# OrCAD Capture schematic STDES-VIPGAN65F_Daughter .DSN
size A3
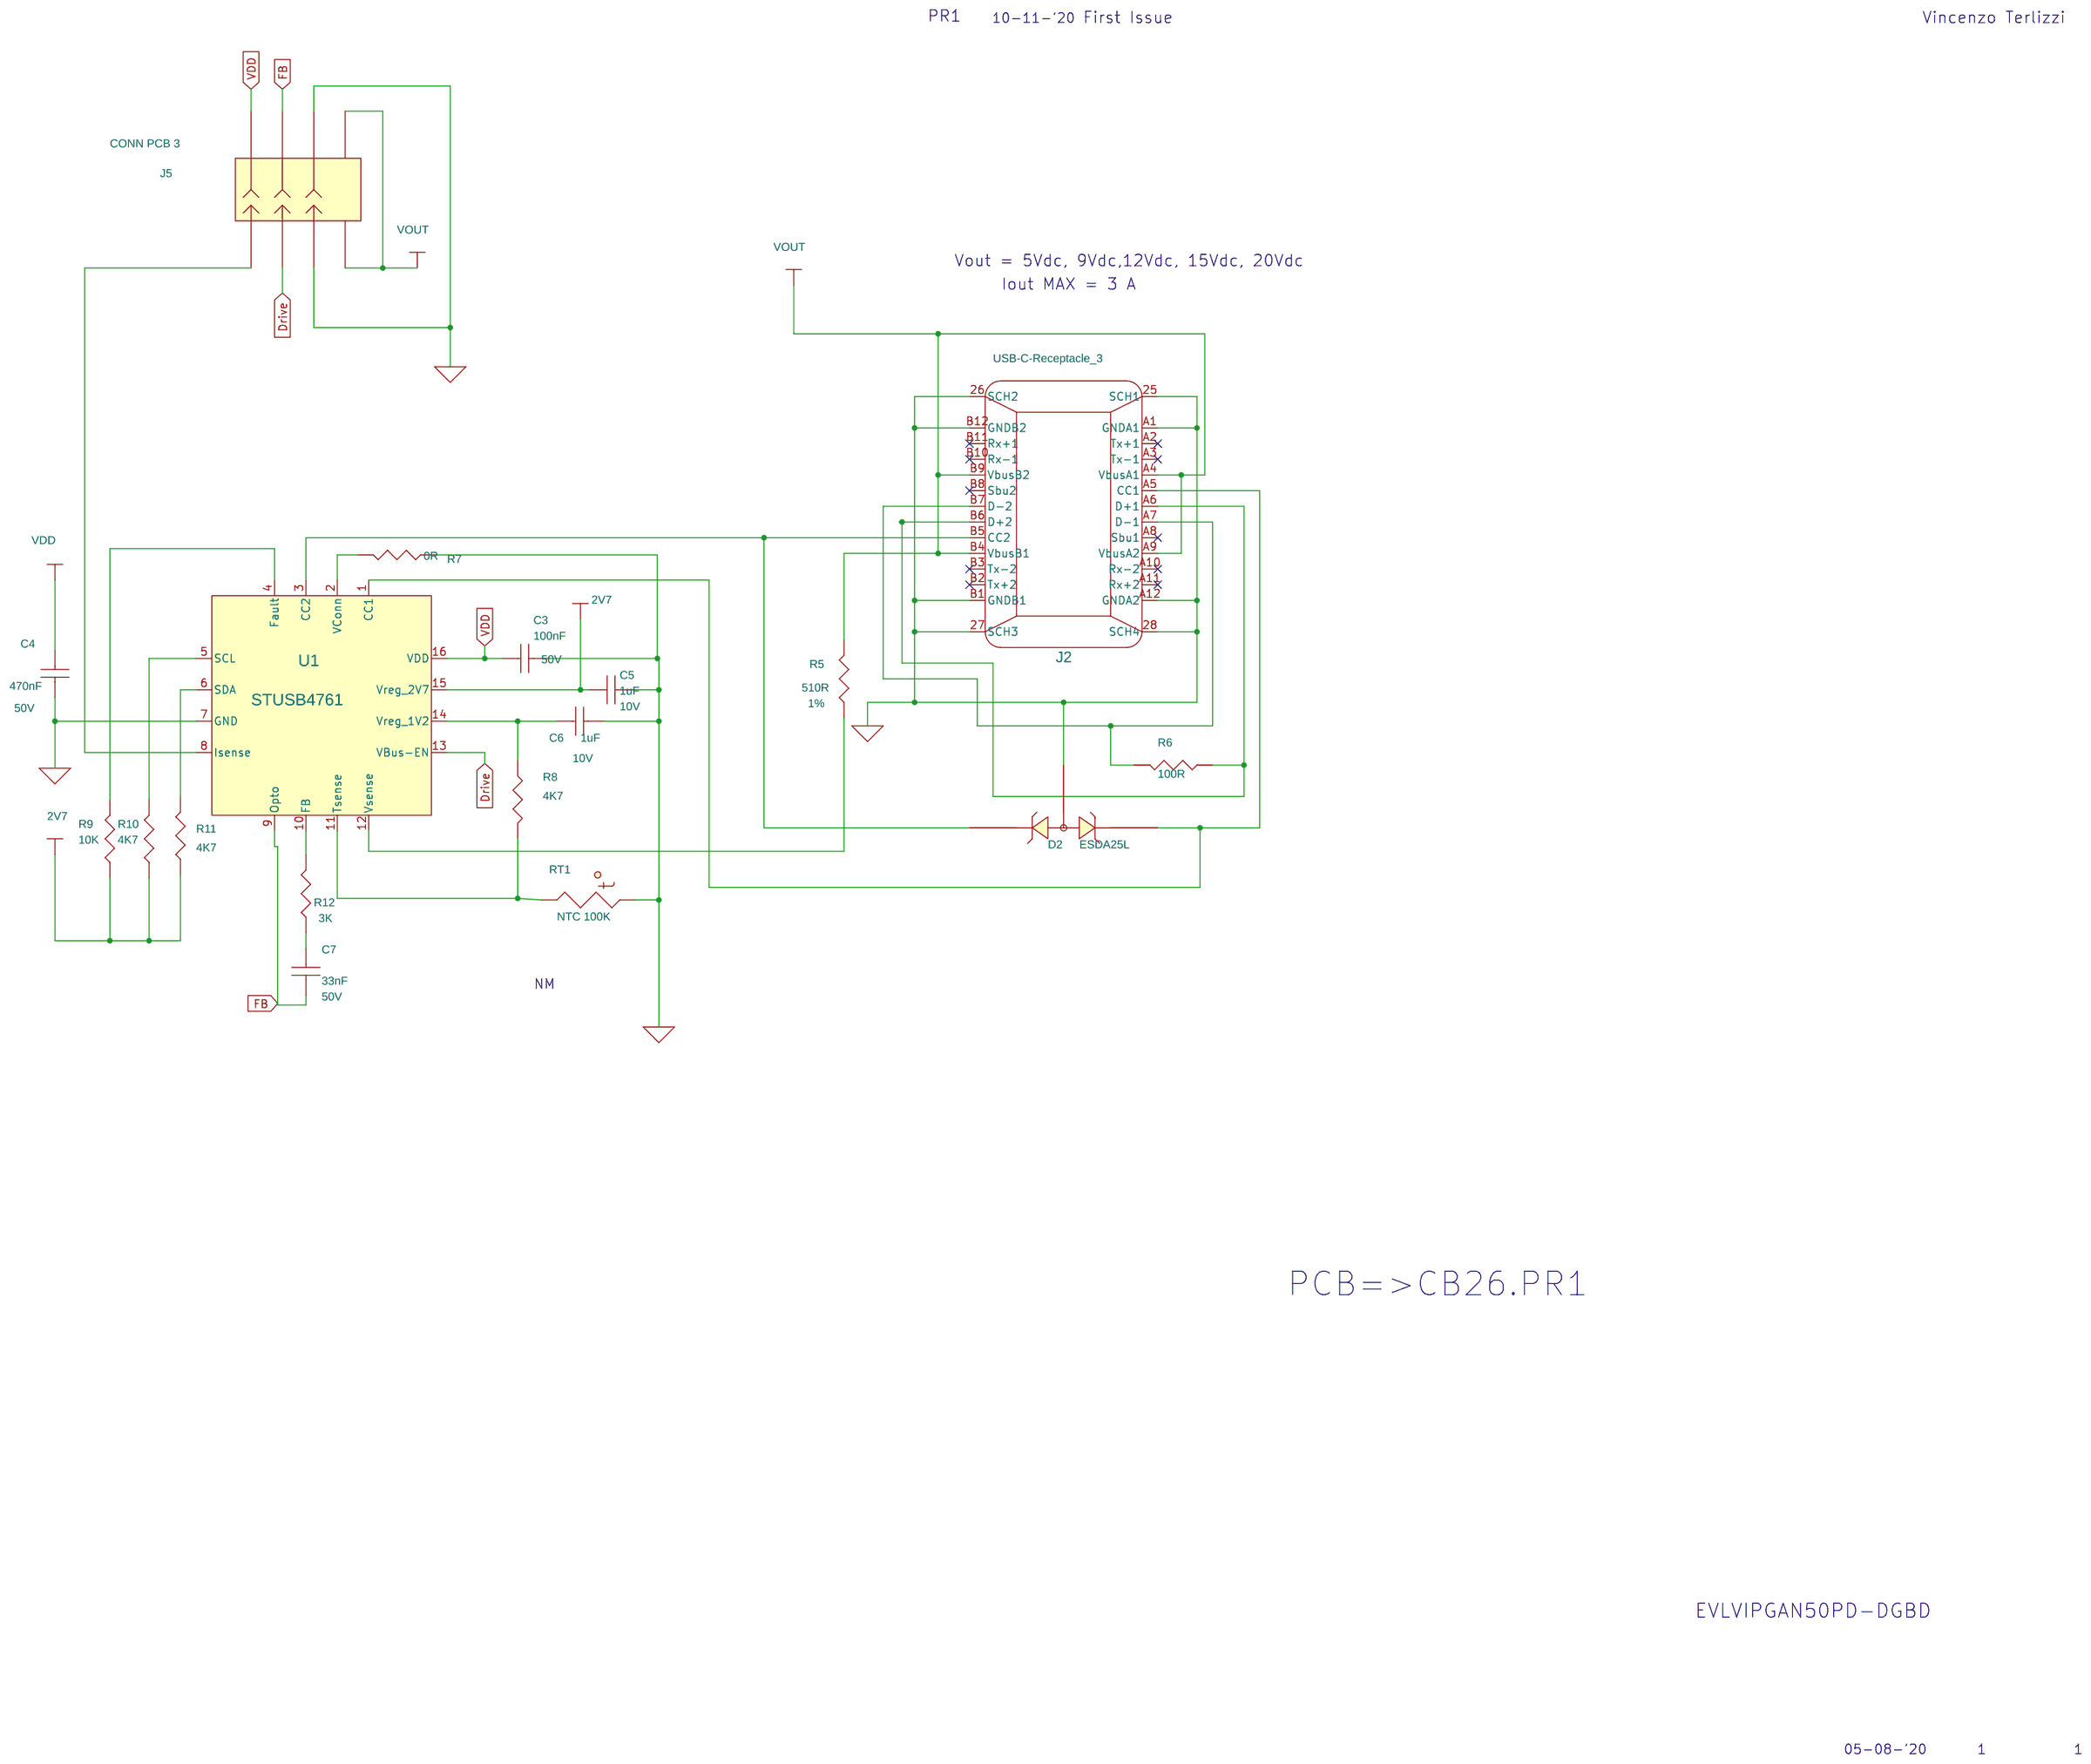
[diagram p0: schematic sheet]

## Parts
C3  100nF  [C_0402]
C4  470nF  [C_0603]
C5  1uF  [C_0402]
C6  1uF  [C_0402]
C7  33nF  [R_0402]
D2  ESDA25L  [sot23st]
J2  USB-C-Receptacle_3  [usbcsmtmolex_new]
J5  CONN PCB 3  [PD_sBOARD]
R5  510R  [R_0402]
R6  100R  [R_0402]
R7  0R  [R_0402]
R8  4K7  [R_0402]
R9  10K  [R_0402]
R10  4K7  [R_0402]
R11  4K7  [R_0402]
R12  3K  [R_0402]
RT1  NTC 100K  [R_0603]
U1  STUSB4761  [qfn16]

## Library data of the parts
C3 = CAP_NP: Multilayer Ceramic X7R   0.1uF       50V  10%; MFG: Kemet; MFG - Code: C0603C104K5RACTU; Manufacturer: Kemet; Manufacturer PN: C0603C104K5RACTU; Rating: 50V; Technology: Multilayer Ceramic Capacitor X7R; Tolerance: 10%
C4 = CAP_NP: Multilayer Ceramic X7R   0.47uF     50V  10%; MFG: AVX; MFG - Code: 08055C474K4T2A; Manufacturer: AVX; Manufacturer PN: 08055C474K4T2A; Rating: 50V; Technology: Multilayer Ceramic Capacitor X7R; Tolerance: 10%
C5 C6 = CAP_NP: Multilayer Ceramic X7R    1uF         50V  10%; MFG: Kemet; MFG - Code: C0805C105J4RACTU; Manufacturer: Kemet; Manufacturer PN: C0805C105J4RACTU; Rating: 10V; Technology: Multilayer Ceramic Capacitor X7R; Tolerance: 10%
C7 = CAP_NP: Multilayer Ceramic X7R   0.033uF   50V 10%; MFG: Kemet; Manufacturer: Kemet; Manufacturer PN: C0603X333K5X7RAC; Rating: 50V; Technology: Multilayer Ceramic Capacitor X7R; Tolerance: 10%
D2 = DIODE_DUAL_CA_JKK_2: Dual Transil   10mA - 1.2V; Manufacturer: STMicroelectronics
J2 = USB-C-Receptacle_6: Connector USB 3.1,type C,  90°,  DC OUT; Manufacturer: MOLEX; Manufacturer PN: 2012670005
J5 = CONN_PCB_3_1
R5 = RESISTOR: Thick Film Chip    510R     0.0625W   1%; MFG: Yageo; MFG - Code: RC0603FR-07510RL; Manufacturer: Yageo; Manufacturer PN: RC0603FR-07510RL; Rating: 0.0625W; Technology: Thick Film Chip Resistor; Tolerance: 1%
R6 = RESISTOR: Thick Film Chip    100R     0.0625W   1%; MFG: Yageo; MFG - Code: RC0603FR-07100RL; Manufacturer: Yageo; Manufacturer PN: RC0603FR-07100RL; Rating: 0.0625W; Supplier: RS; Technology: Thick Film Chip Resistor; Tolerance: 1%
R7 = RESISTOR: Thick Film Chip        0R        0.125W   5%; MFG: Vishay; MFG - Code: CRCW06030000Z0EA; Manufacturer: Vishay; Manufacturer PN: CRCW08050000JKEA; Rating: 0.0625W; Supplier: RS; Technology: Thick Film Chip Resistor; Tolerance: 5%
R8 = RESISTOR: Thick Film Chip     4.7k     0.0625W   5%; MFG: Vishay; MFG - Code: CRCW06034K70JKEA; Manufacturer: Vishay; Manufacturer PN: CRCW06034K70JKEA; Rating: 0.0625W; Supplier: RS; Technology: Thick Film Chip Resistor; Tolerance: 5%
R9 = RESISTOR: Thick Film Chip      10k     0.0625W   5%; MFG: Vishay; MFG - Code: CRCW060310K0JKEA; Manufacturer: Vishay; Manufacturer PN: CRCW060310K0JKEA; Rating: 0.0625W; Supplier: RS; Technology: Thick Film Chip Resistor; Tolerance: 5%
R10 R11 = RESISTOR: Thick Film Chip     4.7k     0.0625W   5%; MFG: Vishay; MFG - Code: CRCW060310K0JKEA; Manufacturer: Vishay; Manufacturer PN: CRCW06034K70JKEA; Rating: 0.0625W; Supplier: RS; Technology: Thick Film Chip Resistor; Tolerance: 5%
R12 = RESISTOR: Thick Film Chip         3k     0.0625W  5%; MFG: Vishay; MFG - Code: CRCW06033K0JKEA; Manufacturer: Vishay; Manufacturer PN: CRCW06033K0JKEA; Rating: 0.0625W; Technology: Thick Film Chip Resistor; Tolerance: 5%
RT1 = NTC: NTC 100K    100mW    1%; Manufacturer: Vishay; Manufacturer PN: NTCS0603E3104FXT
U1 = STUSB4761_0: USB PD  Controller  STUSB4761; Manufacturer: STMicroelectronic

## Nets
2V7: C5.1 R9.2 R10.1 R11.1 U1.15(Vreg_2V7)
GND_SIGNAL: C3.2 C4.2 C5.2 C6.2 D2.3 J2.25(SCH1) J2.26(SCH2) J2.27(SCH3) J2.28(SCH4) J2.A1(GNDA1) J2.A12(GNDA2) J2.B1(GNDB1) J2.B12(GNDB2) J5.3 J5.4 R7.1 RT1.2 U1.7(GND)
Vdd: C3.1 C4.1 J5.8 U1.16(VDD)
Drive: J5.5 U1.13(VBus-EN)
FB: C7.2 J5.6 U1.9(Opto)
Vout: J2.A4(VbusA1) J2.A9(VbusA2) J2.B4(VbusB1) J2.B9(VbusB2) J5.1 J5.2 R5.1
N12284642: J2.A6(D+1) J2.B6(D+2) R6.1
N12284658: J2.A7(D-1) J2.B7(D-2) R6.2
N12286218: D2.1 J2.B5(CC2) U1.3(CC2)
N12286232: D2.2 J2.A5(CC1) U1.1(CC1)
N12312816: R12.2 U1.10(FB)
N12312820: C7.1 R12.1
N12313623: R11.2 U1.6(SDA)
N12313630: R10.2 U1.5(SCL)
N12314144: R8.2 RT1.1 U1.11(Tsense)
N12315159: C6.1 R8.1 U1.14(Vreg_1V2)
N12316115: R9.1 U1.4(Fault)
N12337768: R5.2 U1.12(Vsense)
N16800338: R7.2 U1.2(VConn)
N16810216: J5.7 U1.8(Isense)

Not connected (* = marked no-connect by the designer): J2 A2(Tx+1)* A3(Tx-1)* A8(Sbu1)* A10(Rx-2)* A11(Rx+2)* B2(Tx+2)* B3(Tx-2)* B8(Sbu2)* B10(Rx-1)* B11(Rx+1)*

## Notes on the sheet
- PR1
- 10-11-'20
- First Issue
- Vincenzo Terlizzi
- Vout = 5Vdc, 9Vdc,12Vdc, 15Vdc, 20Vdc
- Iout MAX = 3 A
- NM
- PCB=>CB26.PR1
- EVLVIPGAN50PD-DGBD
- 05-08-'20
- 1            1
